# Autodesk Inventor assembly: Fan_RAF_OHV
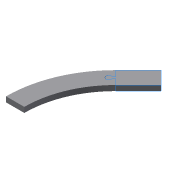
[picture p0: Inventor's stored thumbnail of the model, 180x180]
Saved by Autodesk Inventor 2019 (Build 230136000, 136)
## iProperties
Created: 2019-05
Part Number: Fan_RAF_OHV
Material: Všeobecné
Document SubType Name: Assembly
Designer: auR_54
Author: auR_54
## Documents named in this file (3)
- C:\Users\tatulinek\Documents\Inventor\A\Fan_RAF_OHV.iam
- C:\Users\tatulinek\Documents\Inventor\A\D_3325_row.ipt
- C:\Users\tatulinek\Documents\Inventor\A\F_8701_cir.ipt
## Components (2 placed, 2 different names)
1. D_3325_row:1 — Proti sobě:1, Stejný směr:1, Proti sobě:2
2. F_8701_cir:1 — Proti sobě:1, Stejný směr:1, Proti sobě:2
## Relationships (3: Mate 2, Flush 1)
- Proti sobě:1 [Mate]: D_3325_row:1 ↔ F_8701_cir:1
- Stejný směr:1 [Flush]: D_3325_row:1 ↔ F_8701_cir:1
- Proti sobě:2 [Mate]: D_3325_row:1 ↔ F_8701_cir:1
